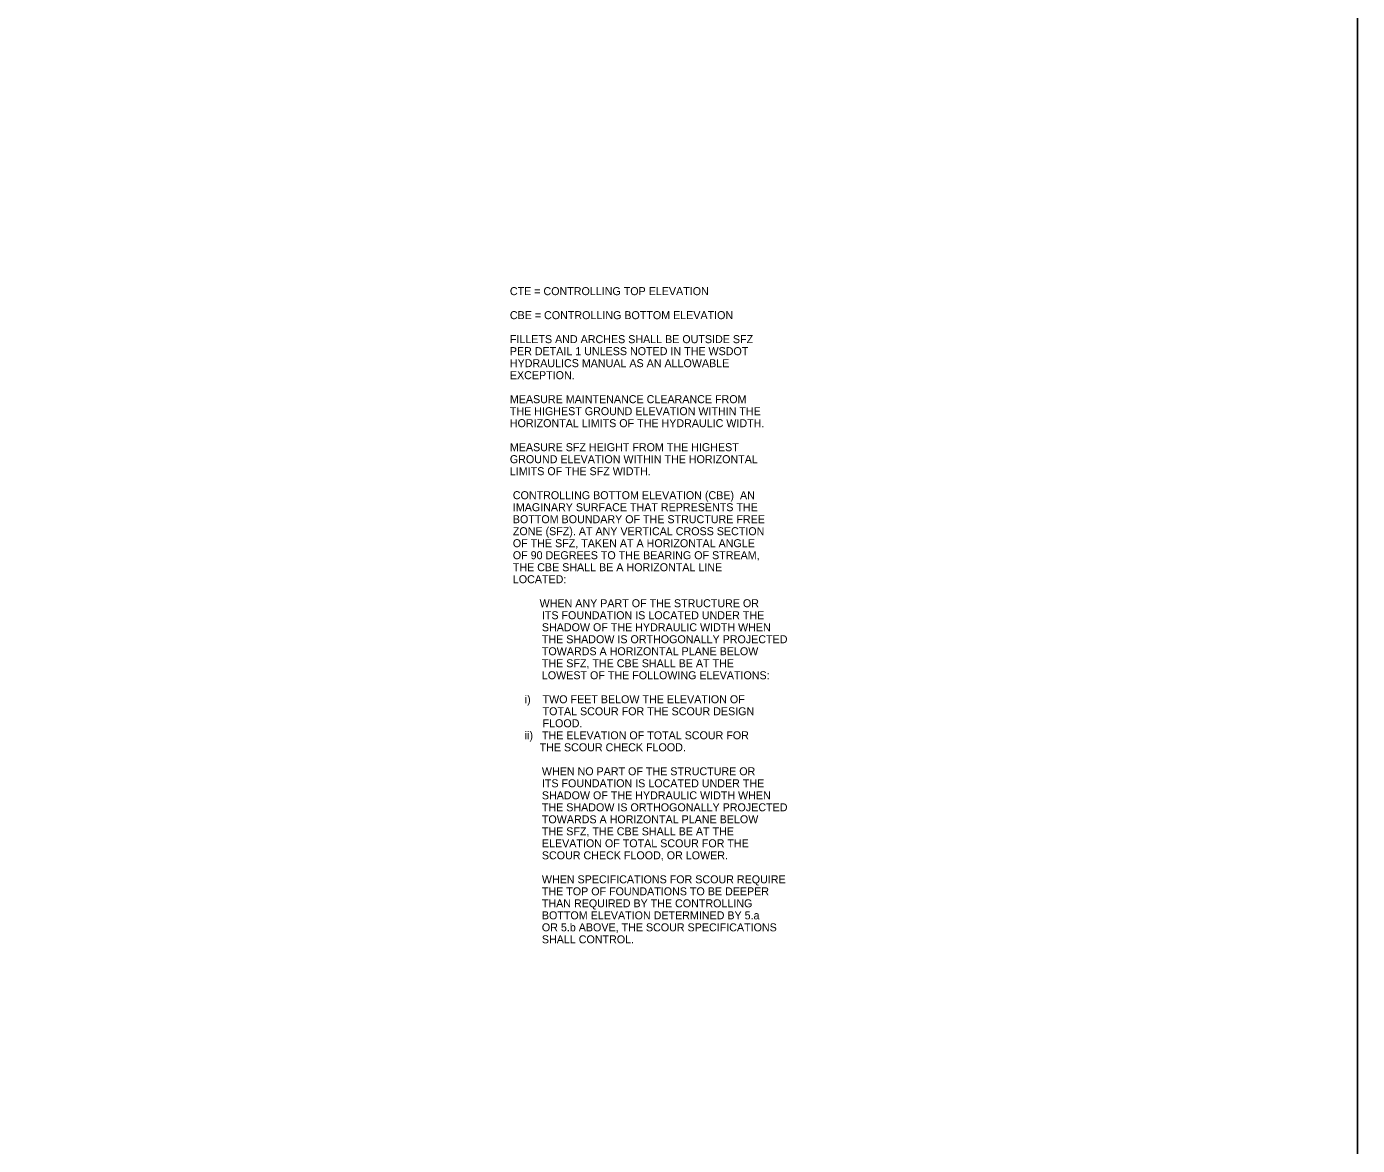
# Model space of a CAD drawing. Extents: x 99988 to 100090, y 99986 to 100024.
# Drawn here: x 100076.44 to 100089.74, y 99999.79 to 100010.98 of the extents above; entities that cross this region are included whole.
import ezdxf

# ---------------------------------------------------------------- set-up
doc = ezdxf.new("R2010")
doc.units = 0
doc.layers.add('Level 1', color=7, linetype='Continuous')
doc.layers.add('Level 2', color=7, linetype='Continuous')

msp = doc.modelspace()

# ---------------------------------------------------------------- linework, layer by layer
at = {"layer": 'Level 2'}
msp.add_lwpolyline([(99987.92, 100023.86), (100089.739, 100023.86), (100089.739, 99988.609), (99987.92, 99988.609)], close=True, dxfattribs=at)

# ---------------------------------------------------------------- texts
at = {"layer": 'Level 1'}
for s, p in [('CTE = CONTROLLING TOP ELEVATION', (100081.267, 100008.293)), ('CBE = CONTROLLING BOTTOM ELEVATION', (100081.267, 100008.053)), ('FILLETS AND ARCHES SHALL BE OUTSIDE SFZ ', (100081.267, 100007.813)), ('PER DETAIL 1 UNLESS NOTED IN THE WSDOT ', (100081.267, 100007.693)), ('HYDRAULICS MANUAL AS AN ALLOWABLE ', (100081.267, 100007.573)), ('EXCEPTION.', (100081.267, 100007.453)), ('THE HIGHEST GROUND ELEVATION WITHIN THE ', (100081.267, 100007.093)), ('MEASURE MAINTENANCE CLEARANCE FROM ', (100081.267, 100007.213)), ('HORIZONTAL LIMITS OF THE HYDRAULIC WIDTH.   ', (100081.267, 100006.973)), ('MEASURE SFZ HEIGHT FROM THE HIGHEST ', (100081.267, 100006.733)), ('GROUND ELEVATION WITHIN THE HORIZONTAL ', (100081.267, 100006.613)), ('LIMITS OF THE SFZ WIDTH.', (100081.267, 100006.493)), (' CONTROLLING BOTTOM ELEVATION (CBE)  AN ', (100081.267, 100006.253)), (' IMAGINARY SURFACE THAT REPRESENTS THE ', (100081.267, 100006.133)), (' ZONE (SFZ). AT ANY VERTICAL CROSS SECTION ', (100081.267, 100005.893)), (' BOTTOM BOUNDARY OF THE STRUCTURE FREE ', (100081.267, 100006.013)), (' OF THE SFZ, TAKEN AT A HORIZONTAL ANGLE ', (100081.267, 100005.773)), (' OF 90 DEGREES TO THE BEARING OF STREAM, ', (100081.267, 100005.653)), (' THE CBE SHALL BE A HORIZONTAL LINE ', (100081.267, 100005.533)), (' LOCATED:', (100081.267, 100005.413)), ('          WHEN ANY PART OF THE STRUCTURE OR ', (100081.267, 100005.173)), ('ITS FOUNDATION IS LOCATED UNDER THE ', (100081.587, 100005.053)), ('SHADOW OF THE HYDRAULIC WIDTH WHEN ', (100081.587, 100004.933)), ('THE SHADOW IS ORTHOGONALLY PROJECTED ', (100081.587, 100004.813)), ('TOWARDS A HORIZONTAL PLANE BELOW ', (100081.587, 100004.693)), ('THE SFZ, THE CBE SHALL BE AT THE ', (100081.587, 100004.573)), ('LOWEST OF THE FOLLOWING ELEVATIONS:', (100081.587, 100004.453)), ('     i)    TWO FEET BELOW THE ELEVATION OF ', (100081.267, 100004.213)), ('           TOTAL SCOUR FOR THE SCOUR DESIGN ', (100081.267, 100004.093)), ('           FLOOD.', (100081.267, 100003.973)), ('     ii)   THE ELEVATION OF TOTAL SCOUR FOR ', (100081.267, 100003.853)), ('          THE SCOUR CHECK FLOOD.', (100081.267, 100003.733)), ('WHEN NO PART OF THE STRUCTURE OR ', (100081.587, 100003.493)), ('ITS FOUNDATION IS LOCATED UNDER THE ', (100081.587, 100003.373)), ('SHADOW OF THE HYDRAULIC WIDTH WHEN ', (100081.587, 100003.253)), ('THE SHADOW IS ORTHOGONALLY PROJECTED ', (100081.587, 100003.133)), ('TOWARDS A HORIZONTAL PLANE BELOW ', (100081.587, 100003.013)), ('THE SFZ, THE CBE SHALL BE AT THE ', (100081.587, 100002.893)), ('ELEVATION OF TOTAL SCOUR FOR THE ', (100081.587, 100002.773)), ('SCOUR CHECK FLOOD, OR LOWER.', (100081.587, 100002.653)), ('WHEN SPECIFICATIONS FOR SCOUR REQUIRE ', (100081.587, 100002.413)), ('THE TOP OF FOUNDATIONS TO BE DEEPER ', (100081.587, 100002.293)), ('THAN REQUIRED BY THE CONTROLLING ', (100081.587, 100002.173)), ('BOTTOM ELEVATION DETERMINED BY 5.a', (100081.587, 100002.053)), ('OR 5.b ABOVE, THE SCOUR SPECIFICATIONS ', (100081.587, 100001.933)), ('SHALL CONTROL.          ', (100081.587, 100001.813))]:
    msp.add_text(s, height=0.08, dxfattribs=at).set_placement(p)

doc.saveas('drawing.dxf')
